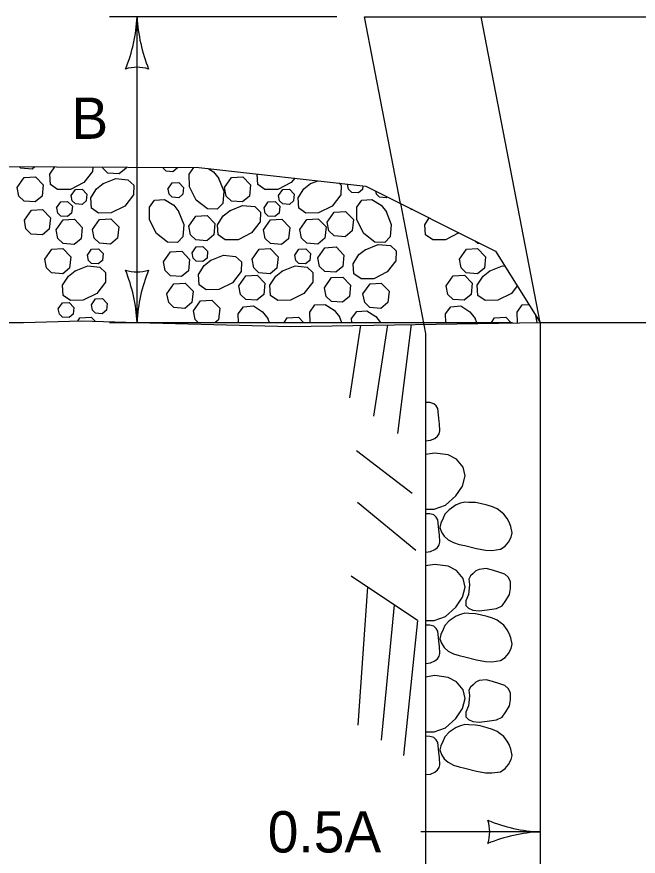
# Model space of a CAD drawing. Extents: x 49991.4 to 50021, y 49987.6 to 50011.4.
# Drawn here: x 50000.205 to 50001.108, y 49996.429 to 49997.65 of the extents above; entities that cross this region are included whole.
import ezdxf

# ---------------------------------------------------------------- set-up
doc = ezdxf.new("R2010")
doc.units = 0
for name, color, linetype in [('Level 1', 7, 'Continuous'), ('Level 2', 7, 'Continuous'), ('Level 3', 7, 'Continuous')]:
    doc.layers.add(name, color=color, linetype=linetype)

msp = doc.modelspace()

# ---------------------------------------------------------------- linework, layer by layer
at = {"layer": 'Level 1'}
for p, q in [((50000.7101, 49997.6503), (50001.8786, 49997.6503)), ((50000.7626, 49997.3788), (50000.7101, 49997.6503)), ((50000.9657, 49997.2058), (50000.8798, 49997.6503)), ((50000.8807, 49997.6503), (50001.7091, 49997.6503)), ((50000.6309, 49997.4073), (50000.6425, 49997.4119)), ((50000.6856, 49997.407), (50000.6857, 49997.4071)), ((50000.7626, 49997.3788), (50000.7991, 49997.1899)), ((50000.78, 49997.37), (50000.7777, 49997.3697)), ((50000.6733, 49997.2148), (50000.6769, 49997.2058)), ((50000.9613, 49997.2057), (50000.9593, 49997.216)), ((50000.3394, 49997.2058), (50000.9257, 49997.2058)), ((50000.5692, 49997.2123), (50000.5718, 49997.2058)), ((50000.7046, 49997.2016), (50000.6885, 49997.0959)), ((50000.7435, 49997.2023), (50000.7233, 49997.0695)), ((50000.7782, 49997.2028), (50000.758, 49997.0445)), ((50000.8707, 49997.2123), (50000.8733, 49997.2058)), ((50000.9259, 49997.2052), (50000.9258, 49997.2054)), ((50000.9657, 49997.2058), (50000.9657, 49994.0392)), ((50000.9657, 49997.2058), (50001.6325, 49997.2058)), ((50000.7991, 49997.1899), (50000.7991, 49994.0392)), ((50000.7796, 49996.9568), (50000.6986, 49997.0189)), ((50000.7848, 49996.8739), (50000.7001, 49996.944)), ((50000.7874, 49996.7723), (50000.691, 49996.8368)), ((50000.7146, 49996.8211), (50000.7007, 49996.6203)), ((50000.7533, 49996.7951), (50000.7344, 49996.5983)), ((50000.7874, 49996.7723), (50000.767, 49996.5759))]:
    msp.add_line(p, q, dxfattribs=at)
for points in [[(49999.839, 49997.443), (50000.1583, 49997.4327), (50000.4695, 49997.431), (50000.712, 49997.4042), (50000.9006, 49997.3093), (50000.9657, 49997.2058)], [(50000.2308, 49997.4323), (50000.2267, 49997.4289), (50000.2106, 49997.4301), (50000.2082, 49997.4324)], [(50000.3149, 49997.4318), (50000.3148, 49997.4254), (50000.3021, 49997.4092), (50000.2824, 49997.3993), (50000.2639, 49997.399), (50000.2535, 49997.4064), (50000.2525, 49997.4212), (50000.2596, 49997.4321)], [(50000.3635, 49997.4316), (50000.3634, 49997.4301), (50000.3533, 49997.4217), (50000.3371, 49997.4229), (50000.3295, 49997.4302), (50000.3292, 49997.4318)], [(50000.4377, 49997.4312), (50000.4376, 49997.4301), (50000.4315, 49997.425), (50000.4218, 49997.4258), (50000.4173, 49997.4302), (50000.4171, 49997.4313)], [(50000.4979, 49997.4157), (50000.5055, 49997.3965), (50000.504, 49997.3789), (50000.496, 49997.3705), (50000.4817, 49997.3708), (50000.4655, 49997.3835), (50000.4557, 49997.4031), (50000.4554, 49997.4216), (50000.4621, 49997.4311)], [(50000.4829, 49997.4295), (50000.4907, 49997.4246), (50000.4984, 49997.4149)], [(50000.6087, 49997.4156), (50000.6036, 49997.4092), (50000.584, 49997.3993), (50000.5655, 49997.399), (50000.5551, 49997.4064), (50000.5541, 49997.4212), (50000.5544, 49997.4216)], [(50000.2051, 49997.4022), (50000.2153, 49997.4167), (50000.2317, 49997.4177), (50000.243, 49997.4059), (50000.2414, 49997.3894), (50000.2313, 49997.381), (50000.2151, 49997.3821), (50000.2075, 49997.3895), (50000.2051, 49997.4022)], [(50000.3294, 49997.4073), (50000.3485, 49997.4149), (50000.3661, 49997.4134), (50000.3745, 49997.4054), (50000.3742, 49997.3912), (50000.3615, 49997.3749), (50000.3419, 49997.3651), (50000.3234, 49997.3648), (50000.313, 49997.3722), (50000.312, 49997.3869), (50000.3205, 49997.4001), (50000.3301, 49997.4078)], [(50000.4244, 49997.3998), (50000.4306, 49997.4086), (50000.4404, 49997.4091), (50000.4472, 49997.402), (50000.4462, 49997.3921), (50000.4402, 49997.3871), (50000.4305, 49997.3878), (50000.4259, 49997.3922), (50000.4245, 49997.3998)], [(50000.5066, 49997.4022), (50000.5169, 49997.4167), (50000.5332, 49997.4177), (50000.5446, 49997.4059), (50000.5429, 49997.3894), (50000.5328, 49997.381), (50000.5167, 49997.3821), (50000.5091, 49997.3895), (50000.5066, 49997.4022)], [(50000.6728, 49997.4086), (50000.6761, 49997.4054), (50000.6758, 49997.3912), (50000.6631, 49997.3749), (50000.6435, 49997.3651), (50000.625, 49997.3648), (50000.6145, 49997.3722), (50000.6136, 49997.3869), (50000.622, 49997.4001), (50000.6317, 49997.4078)], [(50000.2837, 49997.3902), (50000.2898, 49997.399), (50000.2996, 49997.3995), (50000.3065, 49997.3924), (50000.3055, 49997.3825), (50000.2994, 49997.3775), (50000.2897, 49997.3782), (50000.2852, 49997.3826), (50000.2837, 49997.3902)], [(50000.5852, 49997.3902), (50000.5914, 49997.399), (50000.6012, 49997.3995), (50000.608, 49997.3924), (50000.607, 49997.3825), (50000.601, 49997.3775), (50000.5913, 49997.3782), (50000.5867, 49997.3826), (50000.5852, 49997.3902)], [(50000.708, 49997.4047), (50000.7074, 49997.3993), (50000.7014, 49997.3943), (50000.6917, 49997.395), (50000.6871, 49997.3994), (50000.6857, 49997.407)], [(50000.7434, 49997.3884), (50000.7417, 49997.3871), (50000.7321, 49997.3878), (50000.7275, 49997.3922), (50000.7266, 49997.3969)], [(50000.4399, 49997.3673), (50000.4475, 49997.3481), (50000.446, 49997.3305), (50000.4381, 49997.3222), (50000.4238, 49997.3224), (50000.4075, 49997.3351), (50000.3977, 49997.3548), (50000.3974, 49997.3733), (50000.4048, 49997.3837), (50000.4195, 49997.3847), (50000.4327, 49997.3762), (50000.4404, 49997.3665)], [(50000.7415, 49997.3673), (50000.7491, 49997.3481), (50000.7476, 49997.3305), (50000.7396, 49997.3222), (50000.7253, 49997.3224), (50000.7091, 49997.3351), (50000.6993, 49997.3548), (50000.699, 49997.3733), (50000.7064, 49997.3837), (50000.7211, 49997.3847), (50000.7343, 49997.3762), (50000.742, 49997.3665)], [(50000.2625, 49997.3724), (50000.2687, 49997.3812), (50000.2785, 49997.3817), (50000.2853, 49997.3747), (50000.2843, 49997.3648), (50000.2783, 49997.3597), (50000.2686, 49997.3604), (50000.264, 49997.3648), (50000.2626, 49997.3724)], [(50000.5138, 49997.3683), (50000.5329, 49997.3759), (50000.5506, 49997.3744), (50000.5589, 49997.3664), (50000.5587, 49997.3521), (50000.5459, 49997.3359), (50000.5263, 49997.3261), (50000.5078, 49997.3257), (50000.4974, 49997.3331), (50000.4964, 49997.3479), (50000.5049, 49997.361), (50000.5146, 49997.3688)], [(50000.5641, 49997.3724), (50000.5702, 49997.3812), (50000.5801, 49997.3817), (50000.5869, 49997.3747), (50000.5859, 49997.3648), (50000.5798, 49997.3597), (50000.5701, 49997.3604), (50000.5656, 49997.3648), (50000.5641, 49997.3724)], [(50000.2155, 49997.3544), (50000.2257, 49997.3689), (50000.2421, 49997.3699), (50000.2534, 49997.3581), (50000.2518, 49997.3415), (50000.2417, 49997.3331), (50000.2255, 49997.3343), (50000.2179, 49997.3417), (50000.2155, 49997.3543)], [(50000.4547, 49997.3458), (50000.4649, 49997.3604), (50000.4813, 49997.3613), (50000.4927, 49997.3495), (50000.491, 49997.333), (50000.4809, 49997.3246), (50000.4648, 49997.3258), (50000.4572, 49997.3331), (50000.4547, 49997.3458)], [(50000.656, 49997.3517), (50000.6663, 49997.3663), (50000.6826, 49997.3672), (50000.694, 49997.3554), (50000.6923, 49997.3389), (50000.6822, 49997.3305), (50000.6661, 49997.3317), (50000.6585, 49997.339), (50000.656, 49997.3517)], [(50000.2619, 49997.3404), (50000.2721, 49997.355), (50000.2885, 49997.3559), (50000.2998, 49997.3441), (50000.2982, 49997.3276), (50000.2881, 49997.3192), (50000.2719, 49997.3204), (50000.2643, 49997.3277), (50000.2619, 49997.3404)], [(50000.3147, 49997.341), (50000.325, 49997.3556), (50000.3413, 49997.3565), (50000.3527, 49997.3447), (50000.3511, 49997.3282), (50000.3409, 49997.3198), (50000.3248, 49997.321), (50000.3172, 49997.3283), (50000.3147, 49997.341)], [(50000.5634, 49997.3404), (50000.5737, 49997.355), (50000.59, 49997.3559), (50000.6014, 49997.3441), (50000.5997, 49997.3276), (50000.5896, 49997.3192), (50000.5735, 49997.3204), (50000.5659, 49997.3277), (50000.5634, 49997.3404)], [(50000.6163, 49997.341), (50000.6265, 49997.3556), (50000.6429, 49997.3565), (50000.6543, 49997.3447), (50000.6526, 49997.3282), (50000.6425, 49997.3198), (50000.6263, 49997.321), (50000.6188, 49997.3283), (50000.6163, 49997.341)], [(50000.8476, 49997.336), (50000.8475, 49997.3359), (50000.8279, 49997.3261), (50000.8094, 49997.3257), (50000.799, 49997.3331), (50000.798, 49997.3479), (50000.8043, 49997.3577)], [(50000.8791, 49997.3201), (50000.875, 49997.3204), (50000.8713, 49997.324)], [(50000.2451, 49997.2977), (50000.2553, 49997.3123), (50000.2717, 49997.3132), (50000.283, 49997.3014), (50000.2814, 49997.2849), (50000.2713, 49997.2765), (50000.2551, 49997.2777), (50000.2475, 49997.2851), (50000.2451, 49997.2977)], [(50000.3072, 49997.3037), (50000.3134, 49997.3125), (50000.3232, 49997.313), (50000.33, 49997.3059), (50000.329, 49997.296), (50000.323, 49997.291), (50000.3133, 49997.2917), (50000.3087, 49997.2961), (50000.3072, 49997.3037)], [(50000.4594, 49997.3071), (50000.4655, 49997.3158), (50000.4753, 49997.3164), (50000.4821, 49997.3093), (50000.4812, 49997.2994), (50000.4751, 49997.2944), (50000.4654, 49997.2951), (50000.4608, 49997.2995), (50000.4594, 49997.3071)], [(50000.5466, 49997.2977), (50000.5569, 49997.3123), (50000.5732, 49997.3132), (50000.5846, 49997.3014), (50000.5829, 49997.2849), (50000.5728, 49997.2765), (50000.5567, 49997.2777), (50000.5491, 49997.2851), (50000.5466, 49997.2977)], [(50000.6088, 49997.3037), (50000.6149, 49997.3125), (50000.6247, 49997.313), (50000.6316, 49997.3059), (50000.6306, 49997.296), (50000.6245, 49997.291), (50000.6148, 49997.2917), (50000.6103, 49997.2961), (50000.6088, 49997.3037)], [(50000.6424, 49997.2999), (50000.6526, 49997.3145), (50000.669, 49997.3155), (50000.6803, 49997.3037), (50000.6787, 49997.2871), (50000.6686, 49997.2787), (50000.6524, 49997.2799), (50000.6448, 49997.2873), (50000.6424, 49997.2999)], [(50000.7111, 49997.3116), (50000.7303, 49997.3192), (50000.7479, 49997.3177), (50000.7562, 49997.3097), (50000.756, 49997.2954), (50000.7433, 49997.2792), (50000.7237, 49997.2694), (50000.7052, 49997.2691), (50000.6947, 49997.2765), (50000.6938, 49997.2912), (50000.7022, 49997.3044), (50000.7119, 49997.3121)], [(50000.8482, 49997.2977), (50000.8584, 49997.3123), (50000.8748, 49997.3132), (50000.8861, 49997.3014), (50000.8845, 49997.2849), (50000.8744, 49997.2765), (50000.8582, 49997.2777), (50000.8506, 49997.2851), (50000.8482, 49997.2977)], [(50000.4178, 49997.2938), (50000.4281, 49997.3083), (50000.4444, 49997.3093), (50000.4558, 49997.2975), (50000.4541, 49997.281), (50000.444, 49997.2725), (50000.4279, 49997.2737), (50000.4203, 49997.2811), (50000.4178, 49997.2938)], [(50000.4859, 49997.2959), (50000.5051, 49997.3035), (50000.5227, 49997.3019), (50000.5311, 49997.294), (50000.5308, 49997.2797), (50000.5181, 49997.2635), (50000.4985, 49997.2536), (50000.48, 49997.2533), (50000.4696, 49997.2607), (50000.4686, 49997.2755), (50000.477, 49997.2886), (50000.4867, 49997.2964)], [(50000.2885, 49997.2804), (50000.3076, 49997.288), (50000.3253, 49997.2864), (50000.3336, 49997.2785), (50000.3334, 49997.2642), (50000.3207, 49997.248), (50000.301, 49997.2382), (50000.2825, 49997.2378), (50000.2721, 49997.2452), (50000.2711, 49997.26), (50000.2796, 49997.2731), (50000.2893, 49997.2809)], [(50000.59, 49997.2804), (50000.6092, 49997.288), (50000.6268, 49997.2864), (50000.6352, 49997.2785), (50000.6349, 49997.2642), (50000.6222, 49997.248), (50000.6026, 49997.2382), (50000.5841, 49997.2378), (50000.5737, 49997.2452), (50000.5727, 49997.26), (50000.5811, 49997.2731), (50000.5908, 49997.2809)], [(50000.8916, 49997.2804), (50000.9108, 49997.288), (50000.9142, 49997.2877)], [(50000.5273, 49997.2592), (50000.5376, 49997.2737), (50000.5539, 49997.2747), (50000.5653, 49997.2629), (50000.5637, 49997.2464), (50000.5536, 49997.238), (50000.5374, 49997.2391), (50000.5298, 49997.2465), (50000.5273, 49997.2592)], [(50000.8289, 49997.2592), (50000.8391, 49997.2737), (50000.8555, 49997.2747), (50000.8669, 49997.2629), (50000.8652, 49997.2464), (50000.8551, 49997.238), (50000.839, 49997.2391), (50000.8314, 49997.2465), (50000.8289, 49997.2592)], [(50000.9323, 49997.2589), (50000.9238, 49997.248), (50000.9041, 49997.2382), (50000.8856, 49997.2378), (50000.8752, 49997.2452), (50000.8742, 49997.26), (50000.8827, 49997.2731), (50000.8924, 49997.2809)], [(50000.4229, 49997.2474), (50000.4331, 49997.262), (50000.4495, 49997.2629), (50000.4609, 49997.2511), (50000.4592, 49997.2346), (50000.4491, 49997.2262), (50000.433, 49997.2273), (50000.4254, 49997.2347), (50000.4229, 49997.2474)], [(50000.652, 49997.2563), (50000.6622, 49997.2709), (50000.6786, 49997.2718), (50000.69, 49997.26), (50000.6883, 49997.2435), (50000.6782, 49997.2351), (50000.6621, 49997.2363), (50000.6545, 49997.2436), (50000.652, 49997.2563)], [(50000.708, 49997.2474), (50000.7183, 49997.262), (50000.7346, 49997.2629), (50000.746, 49997.2511), (50000.7443, 49997.2346), (50000.7342, 49997.2262), (50000.7181, 49997.2273), (50000.7105, 49997.2347), (50000.708, 49997.2474)], [(50000.313, 49997.2313), (50000.3192, 49997.24), (50000.329, 49997.2406), (50000.3358, 49997.2335), (50000.3348, 49997.2236), (50000.3288, 49997.2185), (50000.3191, 49997.2192), (50000.3145, 49997.2237), (50000.313, 49997.2312)], [(50000.4616, 49997.2226), (50000.4719, 49997.2372), (50000.4882, 49997.2381), (50000.4996, 49997.2263), (50000.498, 49997.2098), (50000.4932, 49997.2058)], [(50000.2649, 49997.2255), (50000.2711, 49997.2342), (50000.2809, 49997.2348), (50000.2877, 49997.2277), (50000.2867, 49997.2178), (50000.2807, 49997.2128), (50000.271, 49997.2135), (50000.2664, 49997.2179), (50000.2649, 49997.2255)], [(50000.5269, 49997.2058), (50000.5266, 49997.2183), (50000.534, 49997.2287), (50000.5488, 49997.2297), (50000.562, 49997.2212), (50000.5697, 49997.2115)], [(50000.631, 49997.2058), (50000.6308, 49997.2207), (50000.6382, 49997.2312), (50000.6529, 49997.2321), (50000.6661, 49997.2237), (50000.6738, 49997.214)], [(50000.8284, 49997.2058), (50000.8282, 49997.2183), (50000.8356, 49997.2287), (50000.8503, 49997.2297), (50000.8635, 49997.2212), (50000.8712, 49997.2115)], [(50000.9326, 49997.2053), (50000.9323, 49997.2207), (50000.9397, 49997.2312), (50000.9494, 49997.2318)], [(50000.2931, 49997.2078), (50000.2963, 49997.2124), (50000.3126, 49997.2133), (50000.3184, 49997.2074)], [(50000.4684, 49997.2058), (50000.4641, 49997.2099), (50000.4616, 49997.2226)], [(50000.5932, 49997.2058), (50000.5978, 49997.2124), (50000.6142, 49997.2133), (50000.6214, 49997.2058)], [(50000.6916, 49997.2058), (50000.6915, 49997.2114), (50000.6989, 49997.2219), (50000.7137, 49997.2228), (50000.7268, 49997.2144), (50000.7337, 49997.2058)], [(50000.8948, 49997.2058), (50000.8994, 49997.2124), (50000.9157, 49997.2133), (50000.923, 49997.2058)], [(49999.8762, 49997.2058), (50000.0344, 49997.2008), (50000.0852, 49997.2058), (50000.2144, 49997.2058), (50000.2979, 49997.2079), (50000.3794, 49997.2058), (50000.6028, 49997.2), (50000.9657, 49997.2058)], [(50000.7991, 49997.0337), (50000.7996, 49997.0337), (50000.8063, 49997.0346), (50000.8127, 49997.0372), (50000.8166, 49997.0404), (50000.8188, 49997.044), (50000.82, 49997.048), (50000.8191, 49997.0585), (50000.8183, 49997.0659), (50000.8178, 49997.0713), (50000.8168, 49997.0805), (50000.8146, 49997.0843), (50000.8112, 49997.0876), (50000.8053, 49997.0892), (50000.7991, 49997.0894)], [(50000.7991, 49996.9342), (50000.8115, 49996.9342), (50000.8278, 49996.9401), (50000.8431, 49996.9535), (50000.8529, 49996.9678), (50000.8568, 49996.9826), (50000.8539, 49996.9952), (50000.844, 49997.0068), (50000.8317, 49997.0131), (50000.8125, 49997.0157), (50000.7991, 49997.0136)], [(50000.7991, 49996.8718), (50000.7996, 49996.8718), (50000.8063, 49996.8727), (50000.8127, 49996.8754), (50000.8166, 49996.8785), (50000.8188, 49996.8821), (50000.82, 49996.8862), (50000.8191, 49996.8967), (50000.8183, 49996.9041), (50000.8178, 49996.9094), (50000.8168, 49996.9186), (50000.8146, 49996.9224), (50000.8112, 49996.9258), (50000.8053, 49996.9274), (50000.7991, 49996.9275)], [(50000.7991, 49996.7724), (50000.8115, 49996.7724), (50000.8278, 49996.7782), (50000.8431, 49996.7917), (50000.8529, 49996.806), (50000.8568, 49996.8208), (50000.8539, 49996.8333), (50000.844, 49996.845), (50000.8317, 49996.8512), (50000.8125, 49996.8539), (50000.7991, 49996.8518)], [(50000.7991, 49996.71), (50000.7996, 49996.71), (50000.8063, 49996.7109), (50000.8127, 49996.7136), (50000.8166, 49996.7167), (50000.8188, 49996.7203), (50000.82, 49996.7243), (50000.8191, 49996.7348), (50000.8183, 49996.7422), (50000.8178, 49996.7476), (50000.8168, 49996.7568), (50000.8146, 49996.7606), (50000.8112, 49996.7639), (50000.8053, 49996.7655), (50000.7991, 49996.7657)], [(50000.7991, 49996.6106), (50000.8115, 49996.6106), (50000.8278, 49996.6164), (50000.8431, 49996.6298), (50000.8529, 49996.6442), (50000.8568, 49996.6589), (50000.8539, 49996.6715), (50000.844, 49996.6831), (50000.8317, 49996.6894), (50000.8125, 49996.6921), (50000.7991, 49996.6899)], [(50000.7991, 49996.5481), (50000.7996, 49996.5481), (50000.8063, 49996.549), (50000.8127, 49996.5517), (50000.8166, 49996.5549), (50000.8188, 49996.5584), (50000.82, 49996.5625), (50000.8191, 49996.573), (50000.8183, 49996.5804), (50000.8178, 49996.5858), (50000.8168, 49996.5949), (50000.8146, 49996.5987), (50000.8112, 49996.6021), (50000.8053, 49996.6037), (50000.7991, 49996.6039)]]:
    msp.add_lwpolyline(points, dxfattribs=at)
for points in [[(50000.8437, 49996.9403), (50000.8333, 49996.9334), (50000.8269, 49996.9269), (50000.8245, 49996.9209), (50000.821, 49996.9139), (50000.82, 49996.9076), (50000.822, 49996.9009), (50000.826, 49996.8949), (50000.8321, 49996.8897), (50000.8397, 49996.8857), (50000.8479, 49996.883), (50000.856, 49996.8812), (50000.8732, 49996.877), (50000.8863, 49996.8745), (50000.8956, 49996.8743), (50000.9082, 49996.8759), (50000.9148, 49996.8806), (50000.9198, 49996.8864), (50000.9237, 49996.8935), (50000.9249, 49996.8998), (50000.9232, 49996.909), (50000.9207, 49996.9155), (50000.9178, 49996.9204), (50000.9129, 49996.9271), (50000.9074, 49996.9312), (50000.9033, 49996.9345), (50000.8966, 49996.9374), (50000.8885, 49996.9401), (50000.8784, 49996.9426), (50000.8717, 49996.9439), (50000.8621, 49996.9441), (50000.8562, 49996.9446), (50000.8496, 49996.9428)], [(50000.8769, 49996.8467), (50000.8722, 49996.8445), (50000.8681, 49996.8405), (50000.8646, 49996.8373), (50000.8619, 49996.8326), (50000.8629, 49996.8248), (50000.8624, 49996.8192), (50000.8614, 49996.81), (50000.8575, 49996.8008), (50000.8577, 49996.7939), (50000.8614, 49996.7901), (50000.8678, 49996.7874), (50000.8772, 49996.7863), (50000.8885, 49996.7879), (50000.9023, 49996.7896), (50000.9102, 49996.7937), (50000.9158, 49996.8015), (50000.921, 49996.8102), (50000.9227, 49996.819), (50000.9225, 49996.8288), (50000.9193, 49996.8351), (50000.9143, 49996.8398), (50000.9072, 49996.8423), (50000.8964, 49996.8454), (50000.8873, 49996.8479)], [(50000.8437, 49996.7785), (50000.8333, 49996.7716), (50000.8269, 49996.7651), (50000.8245, 49996.759), (50000.821, 49996.7521), (50000.82, 49996.7458), (50000.822, 49996.7391), (50000.826, 49996.733), (50000.8321, 49996.7279), (50000.8397, 49996.7239), (50000.8479, 49996.7212), (50000.856, 49996.7194), (50000.8732, 49996.7151), (50000.8863, 49996.7127), (50000.8956, 49996.7124), (50000.9082, 49996.714), (50000.9148, 49996.7187), (50000.9198, 49996.7245), (50000.9237, 49996.7317), (50000.9249, 49996.738), (50000.9232, 49996.7472), (50000.9207, 49996.7536), (50000.9178, 49996.7586), (50000.9129, 49996.7653), (50000.9074, 49996.7693), (50000.9033, 49996.7727), (50000.8966, 49996.7756), (50000.8885, 49996.7783), (50000.8784, 49996.7807), (50000.8717, 49996.7821), (50000.8621, 49996.7823), (50000.8562, 49996.7828), (50000.8496, 49996.781)], [(50000.8769, 49996.6849), (50000.8722, 49996.6827), (50000.8681, 49996.6786), (50000.8646, 49996.6755), (50000.8619, 49996.6708), (50000.8629, 49996.663), (50000.8624, 49996.6574), (50000.8614, 49996.6482), (50000.8575, 49996.639), (50000.8577, 49996.6321), (50000.8614, 49996.6283), (50000.8678, 49996.6256), (50000.8772, 49996.6245), (50000.8885, 49996.626), (50000.9023, 49996.6278), (50000.9102, 49996.6318), (50000.9158, 49996.6397), (50000.921, 49996.6484), (50000.9227, 49996.6571), (50000.9225, 49996.667), (50000.9193, 49996.6733), (50000.9143, 49996.678), (50000.9072, 49996.6804), (50000.8964, 49996.6836), (50000.8873, 49996.686)], [(50000.8437, 49996.6167), (50000.8333, 49996.6097), (50000.8269, 49996.6032), (50000.8245, 49996.5972), (50000.821, 49996.5902), (50000.82, 49996.584), (50000.822, 49996.5773), (50000.826, 49996.5712), (50000.8321, 49996.5661), (50000.8397, 49996.562), (50000.8479, 49996.5593), (50000.856, 49996.5575), (50000.8732, 49996.5533), (50000.8863, 49996.5508), (50000.8956, 49996.5506), (50000.9082, 49996.5522), (50000.9148, 49996.5569), (50000.9198, 49996.5627), (50000.9237, 49996.5699), (50000.9249, 49996.5761), (50000.9232, 49996.5853), (50000.9207, 49996.5918), (50000.9178, 49996.5967), (50000.9129, 49996.6035), (50000.9074, 49996.6075), (50000.9033, 49996.6108), (50000.8966, 49996.6138), (50000.8885, 49996.6164), (50000.8784, 49996.6189), (50000.8717, 49996.6202), (50000.8621, 49996.6205), (50000.8562, 49996.6209), (50000.8496, 49996.6191)]]:
    msp.add_lwpolyline(points, close=True, dxfattribs=at)
at = {"layer": 'Level 3'}
for p, q in [((50000.6701, 49997.6503), (50000.3394, 49997.6503)), ((50000.3794, 49997.2058), (50000.3794, 49997.6503)), ((50000.9657, 49996.4649), (50000.7923, 49996.4649))]:
    msp.add_line(p, q, dxfattribs=at)
for centre, radius, start, end in [((50000.1573, 49997.6595), 0.2223, 337.456, 357.6395), ((50000.6122, 49997.6618), 0.233, 182.8273, 202.0772), ((50000.3794, 49997.5221), 0.0548, 72.1388, 107.8612), ((50000.3794, 49997.334), 0.0548, 252.1388, 287.8612), ((50000.1467, 49997.1943), 0.233, 2.8273, 22.0772), ((50000.6016, 49997.1967), 0.2223, 157.456, 177.6395), ((50000.9749, 49996.687), 0.2223, 247.456, 267.6395), ((50000.8375, 49996.4649), 0.0548, 342.1388, 17.8612), ((50000.9772, 49996.2322), 0.233, 92.8273, 112.0772)]:
    msp.add_arc(centre, radius, start, end, dxfattribs=at)

# ---------------------------------------------------------------- texts
at = {"layer": 'Level 2'}
for s, p in [('B', (50000.2839, 49997.4728)), ('0.5A', (50000.5695, 49996.4349))]:
    msp.add_text(s, height=0.06, dxfattribs=at).set_placement(p)

doc.saveas('drawing.dxf')
